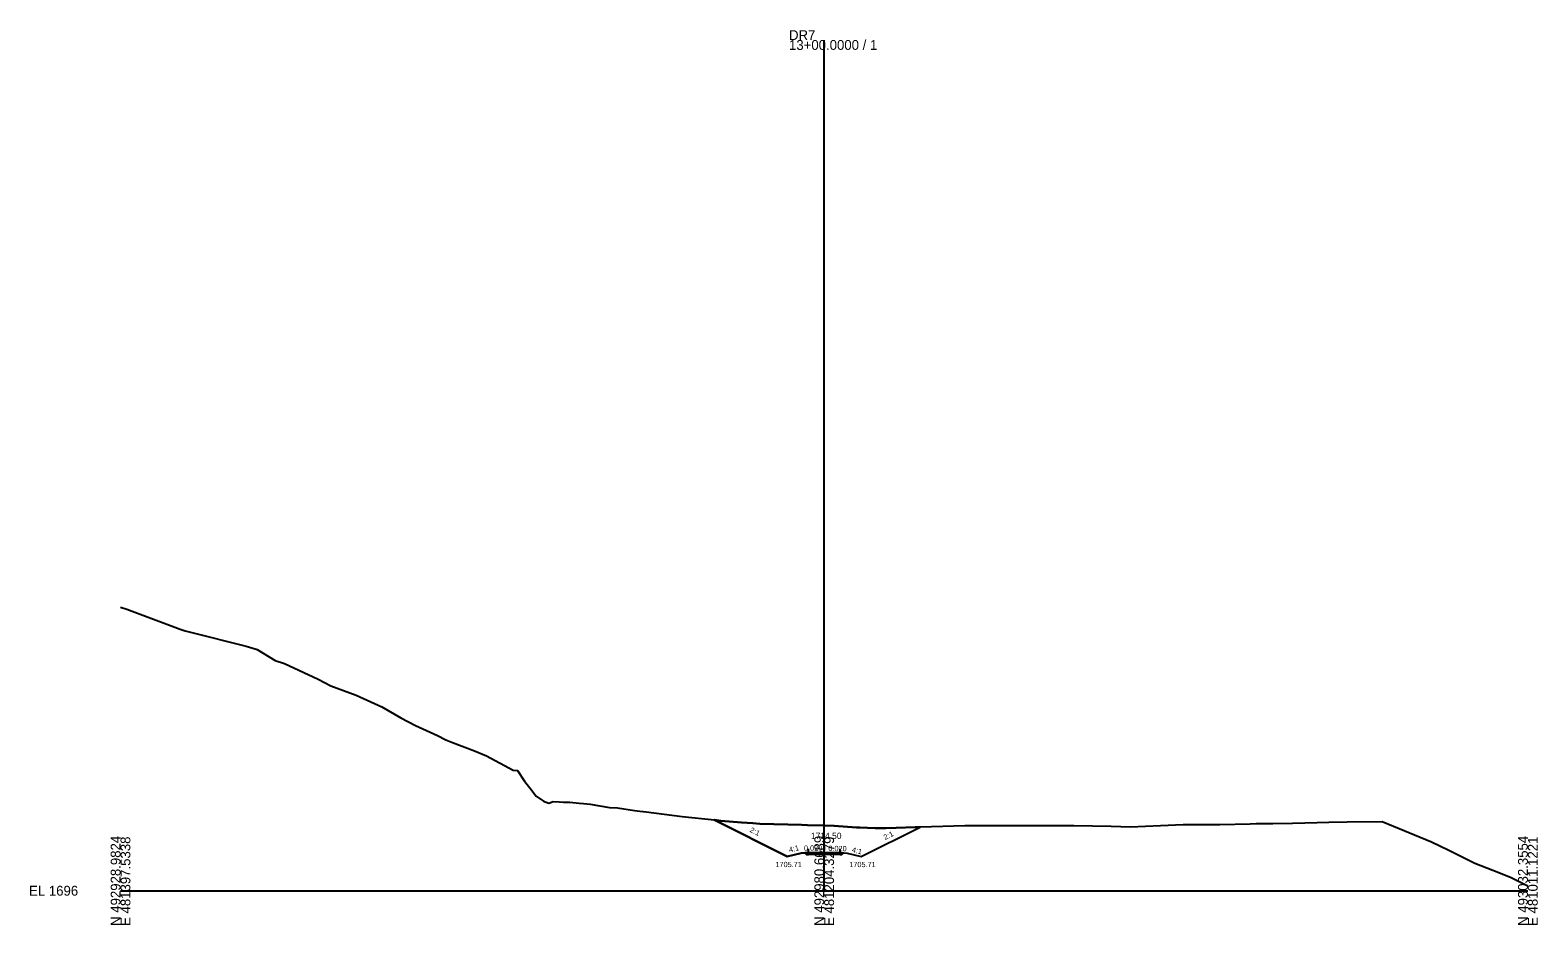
# Model space of a CAD drawing. Extents: x -26 to 403, y -10 to 4215.
# Drawn here: x -25.7 to 402.8, y 2990.3 to 3244.6 of the extents above; entities that cross this region are included whole.
import ezdxf

# ---------------------------------------------------------------- set-up
doc = ezdxf.new("R2010")
doc.units = 0
for name, color, linetype in [('Exist Cross Section Cell', 7, 'Continuous'), ('Exist XS Center Line Elevation Label', 7, 'Continuous'), ('Exist XS Ground Line', 7, 'Continuous'), ('Prop XS Ditch Slope Text', 7, 'Continuous'), ('Prop XS Ditch Standard Text', 7, 'Continuous'), ('Prop XS Dump Level', 7, 'Continuous'), ('Prop XS Earthwork Shape', 7, 'Continuous'), ('Prop XS EOT Tick Mark', 7, 'Continuous'), ('Prop XS Finish Grade', 7, 'Continuous'), ('Prop XS Finish Grade Earthwork', 7, 'Continuous'), ('Prop XS Finish Grade Pavement', 7, 'Continuous'), ('Prop XS Hydro Typical Ditch Data', 7, 'Continuous'), ('Prop XS Pvmt Edge Slope', 7, 'Continuous'), ('Prop XS SE Text', 7, 'Continuous'), ('Prop XS Shoulder Borrow Shape', 7, 'Continuous'), ('Prop XS Side Slope Text', 7, 'Continuous'), ('Prop XS Subgrade Earthwork', 7, 'Continuous')]:
    doc.layers.add(name, color=color, linetype=linetype)

msp = doc.modelspace()

# ---------------------------------------------------------------- linework, layer by layer
at = {"layer": 'Exist Cross Section Cell'}
for p, q in [((200, 3000), (200, 3241.79)), ((0, 3000), (200, 3000)), ((200, 3000), (400, 3000))]:
    msp.add_line(p, q, dxfattribs=at)
at = {"layer": 'Exist XS Ground Line'}
msp.add_lwpolyline([(0, 3080.6), (1.76, 3079.99), (16.92, 3074.34), (18.41, 3073.88), (19.91, 3073.5), (35.74, 3069.55), (38.5, 3068.64), (38.84, 3068.53), (43.92, 3065.48), (46.58, 3064.56), (56.2, 3060.12), (59.79, 3058.28), (66.93, 3055.63), (74.28, 3052.26), (79.66, 3049.16), (83.87, 3047), (90.06, 3044.11), (92.5, 3042.88), (94.37, 3042.18), (100.62, 3039.79), (104, 3038.39), (111.55, 3034.3), (112.85, 3034.21), (114.79, 3031.16), (116.33, 3029.21), (118.11, 3026.87), (120.2, 3025.44), (121.69, 3024.87), (122.99, 3025.35), (124.69, 3025.24), (125.92, 3025.2), (127.71, 3025.13), (130.33, 3024.9), (131.56, 3024.8), (133.44, 3024.59), (138.93, 3023.7), (141.29, 3023.52), (146.05, 3022.81), (147.59, 3022.63), (148.54, 3022.52), (149.36, 3022.4), (159.61, 3021.07), (168.85, 3020.11), (170.64, 3019.87), (176.45, 3019.42), (179.71, 3019.23), (181.71, 3019.05), (189.71, 3018.83), (193.52, 3018.71), (195.28, 3018.61), (200, 3018.5), (202.85, 3018.43), (209.14, 3017.98), (210.14, 3017.93), (214.46, 3017.83), (217.54, 3017.81), (220.49, 3017.9), (225.87, 3018.09), (226.4, 3018.1), (227.35, 3018.12), (239.94, 3018.54), (250.36, 3018.57), (260.64, 3018.56), (264.5, 3018.58), (271, 3018.58), (281.57, 3018.35), (287.04, 3018.2), (295.58, 3018.58), (302.06, 3018.82), (306.9, 3018.84), (312.41, 3018.86), (321.04, 3019.04), (322.77, 3019.07), (327.51, 3019.14), (333.12, 3019.19), (340.1, 3019.35), (343.47, 3019.49), (348.65, 3019.57), (358.6, 3019.65), (372.57, 3013.88), (377.58, 3011.49), (384.89, 3007.84), (391.71, 3005.2), (395.24, 3003.78), (398.06, 3002.33), (400, 3001.37)], dxfattribs=at)
at = {"layer": 'Prop XS Dump Level'}
for p, q in [((195.5, 3010.87), (200, 3010.96)), ((200, 3010.96), (204.5, 3010.87))]:
    msp.add_line(p, q, dxfattribs=at)
at = {"layer": 'Prop XS Earthwork Shape'}
msp.add_lwpolyline([(210.5, 3009.71), (227.3, 3018.11), (226.4, 3018.1), (225.87, 3018.09), (220.49, 3017.9), (217.54, 3017.81), (214.46, 3017.83), (210.14, 3017.93), (209.14, 3017.98), (202.85, 3018.43), (200, 3018.5), (195.28, 3018.61), (193.52, 3018.71), (189.71, 3018.83), (181.71, 3019.05), (179.71, 3019.23), (176.45, 3019.42), (170.64, 3019.87), (168.85, 3020.11), (168.68, 3020.12), (189.5, 3009.71), (193.5, 3010.71), (194.48, 3010.79), (194.95, 3010.32), (195.5, 3010.33), (200, 3010.42), (204.5, 3010.33), (205.05, 3010.32), (205.52, 3010.79), (206.5, 3010.71)], close=True, dxfattribs=at)
at = {"layer": 'Prop XS EOT Tick Mark'}
for p, q in [((195.5, 3010.87), (195.5, 3011.87)), ((204.5, 3010.87), (204.5, 3011.87))]:
    msp.add_line(p, q, dxfattribs=at)
at = {"layer": 'Prop XS Finish Grade'}
for p, q in [((195.5, 3010.87), (194.48, 3010.79)), ((204.5, 3010.87), (205.52, 3010.79))]:
    msp.add_line(p, q, dxfattribs=at)
at = {"layer": 'Prop XS Finish Grade Earthwork'}
for p, q in [((189.5, 3009.71), (168.68, 3020.12)), ((210.5, 3009.71), (227.3, 3018.11)), ((193.5, 3010.71), (189.5, 3009.71)), ((194.48, 3010.79), (193.5, 3010.71)), ((205.52, 3010.79), (206.5, 3010.71)), ((206.5, 3010.71), (210.5, 3009.71))]:
    msp.add_line(p, q, dxfattribs=at)
at = {"layer": 'Prop XS Finish Grade Pavement'}
for p, q in [((195.5, 3010.87), (200, 3010.96)), ((200, 3010.96), (204.5, 3010.87))]:
    msp.add_line(p, q, dxfattribs=at)
at = {"layer": 'Prop XS Hydro Typical Ditch Data'}
for p, q in [((189.5, 3009.71), (168.68, 3020.12)), ((210.5, 3009.71), (227.3, 3018.11)), ((193.5, 3010.71), (189.5, 3009.71)), ((206.5, 3010.71), (210.5, 3009.71))]:
    msp.add_line(p, q, dxfattribs=at)
at = {"layer": 'Prop XS Pvmt Edge Slope'}
for p, q in [((195.5, 3010.87), (194.95, 3010.32)), ((204.5, 3010.87), (205.05, 3010.32))]:
    msp.add_line(p, q, dxfattribs=at)
at = {"layer": 'Prop XS Shoulder Borrow Shape'}
for points in [[(195.5, 3010.87), (194.48, 3010.79), (194.95, 3010.32)], [(195.5, 3010.87), (194.48, 3010.79), (194.95, 3010.32)], [(204.5, 3010.87), (205.52, 3010.79), (205.05, 3010.32)], [(204.5, 3010.87), (205.52, 3010.79), (205.05, 3010.32)]]:
    msp.add_lwpolyline(points, close=True, dxfattribs=at)
at = {"layer": 'Prop XS Subgrade Earthwork'}
for p, q in [((194.95, 3010.32), (194.48, 3010.79)), ((195.5, 3010.33), (194.95, 3010.32)), ((200, 3010.42), (195.5, 3010.33)), ((204.5, 3010.33), (200, 3010.42)), ((204.5, 3010.33), (205.05, 3010.32)), ((205.05, 3010.32), (205.52, 3010.79))]:
    msp.add_line(p, q, dxfattribs=at)

# ---------------------------------------------------------------- texts
at = {"layer": 'Exist Cross Section Cell'}
for s, p in [('DR7', (190, 3241.79)), ('13+00.0000 / 1', (190, 3238.99)), ('EL 1696', (-26, 2998.6))]:
    msp.add_text(s, height=2.8, dxfattribs=at).set_placement(p)
for s, p in [('N 492928.9824', (0, 2990)), ('E 481397.5338', (2.8, 2990)), ('N 492980.6689', (200, 2990)), ('E 481204.3279', (202.8, 2990)), ('N 493032.3554', (400, 2990)), ('E 481011.1221', (402.8, 2990))]:
    msp.add_text(s, height=2.8, rotation=90, dxfattribs=at).set_placement(p)
at = {"layer": 'Exist XS Center Line Elevation Label'}
msp.add_text('1714.50', height=1.8, dxfattribs=at).set_placement((196.23, 3014.7))
at = {"layer": 'Prop XS Ditch Slope Text'}
for rotation, p in [(14.0362, (190.17, 3010.85)), (345.9638, (207.76, 3011))]:
    msp.add_text('4:1', height=1.5, rotation=rotation, dxfattribs=at).set_placement(p)
at = {"layer": 'Prop XS Ditch Standard Text'}
for p in [(186.14, 3006.71), (207.14, 3006.71)]:
    msp.add_text('1705.71', height=1.5, dxfattribs=at).set_placement(p)
at = {"layer": 'Prop XS Dump Level'}
for p in [(193.5, 3010.67), (206.5, 3010.67)]:
    msp.add_text('Case1', height=0.04, dxfattribs=at).set_placement(p)
at = {"layer": 'Prop XS SE Text'}
for rotation, p in [(1.1458, (194.27, 3011.34)), (358.8542, (201.18, 3011.31))]:
    msp.add_text('0.020', height=1.5, rotation=rotation, dxfattribs=at).set_placement(p)
at = {"layer": 'Prop XS Side Slope Text'}
for rotation, p in [(333.4349, (178.7, 3016.79)), (26.5651, (217.31, 3014.38))]:
    msp.add_text('2:1', height=1.5, rotation=rotation, dxfattribs=at).set_placement(p)

doc.saveas('drawing.dxf')
